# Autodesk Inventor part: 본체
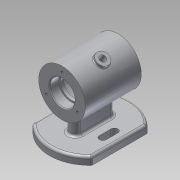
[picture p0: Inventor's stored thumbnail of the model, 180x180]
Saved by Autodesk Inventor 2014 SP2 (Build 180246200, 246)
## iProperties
Created: 2022-02
Part Number: 본체
Material: 알루미늄 6061
Document SubType Name: Modeling
Designer: 거성
Density: 2.71 g/cm^3
Appearance: 알루미늄 - 평지
Author: 거성
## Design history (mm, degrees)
sketch "스케치1"
  geometry: L1 (0, 36)-(0, -36); L2 (16, 36)-(30, 36); L3 (30, 36)-(30, -36); L4 (30, -36)-(16, -36); L5 (16, -36)-(16, -24); L6 (16, -24)-(14, -24); L7 (14, -24)-(14, -20); L8 (14, -20)-(25, -20); L9 (25, -20)-(25, 20); L10 (25, 20)-(14, 20); L11 (14, 20)-(14, 24); L12 (14, 24)-(16, 24); L13 (16, 36)-(16, 24); 2 further points
  constraints: 26 end point, 9 parallel, 3 perpendicular, 2 horizontal alignment, 1 coincident, 1 midpoint, 1 vertical
  dimensions: "d0" = 72 distance of L1.start L1.end; "d1" = 60 diameter of L3 L1; "d2" = 50 diameter of L9 L1; "d3" = 28 diameter of L7 L1; "d4" = 32 diameter of L5 L1; "d5" = 28 diameter of L11 L1; "d6" = 32 diameter of L13 L1; "d7" = 12 distance of L4.end L5.end; "d8" = 12 distance of L2.start L12.end; "d9" = 40 distance of L8.end L9.end; "d10" = 4 distance of L6.end L7.end
revolve "회전1" sketch "스케치1" stored, may be unused: angle "d11" = 90 deg
node "작업 평면1"
sketch "스케치2"
  geometry: L1 (0, 52)-(0, -52); L2 (38, 35.496)-(38, -35.496); L3 (-38, 35.496)-(-38, -35.496); A1 r 52 centre (0, 0) between (38, 35.496) and (38, -35.496); 2 further points
  constraints: 6 end point, 6 point on circle, 2 coincident, 1 centre point, 1 midpoint, 1 vertical
  dimensions: "d13" = 104 diameter of A1; "d17" = 38 distance between parallel lines of L2 L1; "d18" = 38 distance between parallel lines of L3 L1
extrude "돌출1" join sketch "스케치2" distance "d19" = 10; taper "d20" = 0 deg
sketch "스케치3"
  geometry: L1 (-38, 35.496)-(-38, -35.496) reference; L2 (0, -19)-(0, 19); L3 (7, -19)-(7, 19); L4 (-7, 19)-(-7, -19); A1 r 52 centre (0, 0) between (38, 35.496) and (-38, 35.496) reference; A2 r 7 centre (0, -19) between (-7, -19) and (7, -19); A3 r 7 centre (0, 19) between (7, 19) and (-7, 19); 1 further point
  constraints: 8 end point, 4 point on circle, 4 tangent, 2 centre point, 2 parallel, 1 coincident, 1 midpoint
  dimensions: "d21" = 14 diameter of A3; "d22" = 38 distance of L4.start L4.end
extrude "돌출2" join sketch "스케치3" stored distance "d23" = 10; taper "d24" = 0 deg
sketch "스케치4"
  geometry: L1 (-7, -19)-(-7, 19) reference; L2 (-24, -7.5)-(-24, 7.5); L3 (-19.5, -7.5)-(-19.5, 7.5); L4 (-28.5, 7.5)-(-28.5, -7.5); A1 r 52 centre (0, 0) between (38, 35.496) and (-38, 35.496) reference; A2 r 4.5 centre (-24, -7.5) between (-28.5, -7.5) and (-19.5, -7.5); A3 r 4.5 centre (-24, 7.5) between (-19.5, 7.5) and (-28.5, 7.5); 1 further point
  constraints: 8 end point, 4 point on circle, 4 tangent, 2 centre point, 2 parallel, 1 horizontal alignment, 1 midpoint
  dimensions: "d25" = 9 diameter of A3; "d27" = 15 distance of L4.start L4.end; "d28" = 24 distance of A1.centre point (-24, 0)
extrude "돌출3" cut sketch "스케치4" distance "d29" = 10; taper "d30" = 0 deg
fillet "모깎기1" dims "d31" = 3
fillet "모깎기2" dims "d32" = 3
fillet "모깎기3" dims "d33" = 3
fillet "모깎기4" dims "d34" = 0.3
chamfer "모따기1" distance "d35" = 1; stored, may be unused: second distance "d36" = 2, angle "d37" = 45 deg
chamfer "모따기2" distance "d38" = 1; stored, may be unused: second distance "d39" = 2, angle "d40" = 45 deg
sketch "스케치5" dims "d41" = 46
  geometry: L1 (0, 0)-(0, 23); C1 r 17 at (0, 0) reference; 1 further point
  constraints: 2 coincident, 2 end point, 1 vertical, 1 vertical alignment, 2 other
hole "구멍1" sketch "스케치5" at (0, 23) diameter "d42" = 3.242; stored, may be unused: countersink angle "d46" = 90 deg, drill point angle "d48" = 118 deg; dims "d43" = 8, "d44" = 4, "d45" = 2, "d47" = 10
node "작업 평면2"
node "작업 평면3"
node "작업 평면4"
sketch "스케치7"
  geometry: L1 (0, 0)-(0, 32.964); L2 (0, 0)-(28.579, 16.5)
  constraints: 4 end point, 1 vertical
  dimensions: "d63" = 32.96436 distance of L1.start L1.end; "d64" = 33 distance of L1.start L2.end; "d65" = 60 deg angle of L1 L2
node "작업 평면6"
  node "작업 평면5"
node "작업 평면7"
node "작업 평면8"
sketch "스케치9"
  geometry: L1 (0, 0)-(16.5, 28.579); L2 (0, 0)-(33, 0)
  constraints: 4 end point, 1 equal length, 1 horizontal
  dimensions: "d77" = 33 distance of L1.start L1.end; "d78" = 60 deg angle of L2 L1
node "작업 평면9"
sketch "스케치10"
  geometry: C1 r 8 at (0, 0); C2 r 4 at (0, 0); 1 further point
  constraints: 2 centre point, 2 coincident
  dimensions: "d79" = 16 diameter of C1; "d80" = 8 diameter of C2
extrude "돌출6" join sketch "스케치10" stored distance "d81" = 3; taper "d82" = 0 deg
extrude "돌출7" cut sketch "스케치10" stored distance "d83" = 3; taper "d84" = 0 deg
fillet "모깎기5" dims "d85" = 1
node "솔리드1"
mirror "대칭1"
pattern_circular "원형 패턴1" dims angle "d50" = 360 deg
mirror "대칭2"
other parameters: "d12" = -62, "d52" = 0, "d53" = 0, "d57" = 0, "d66" = 90 deg, "d73" = 0, "d74" = 0
